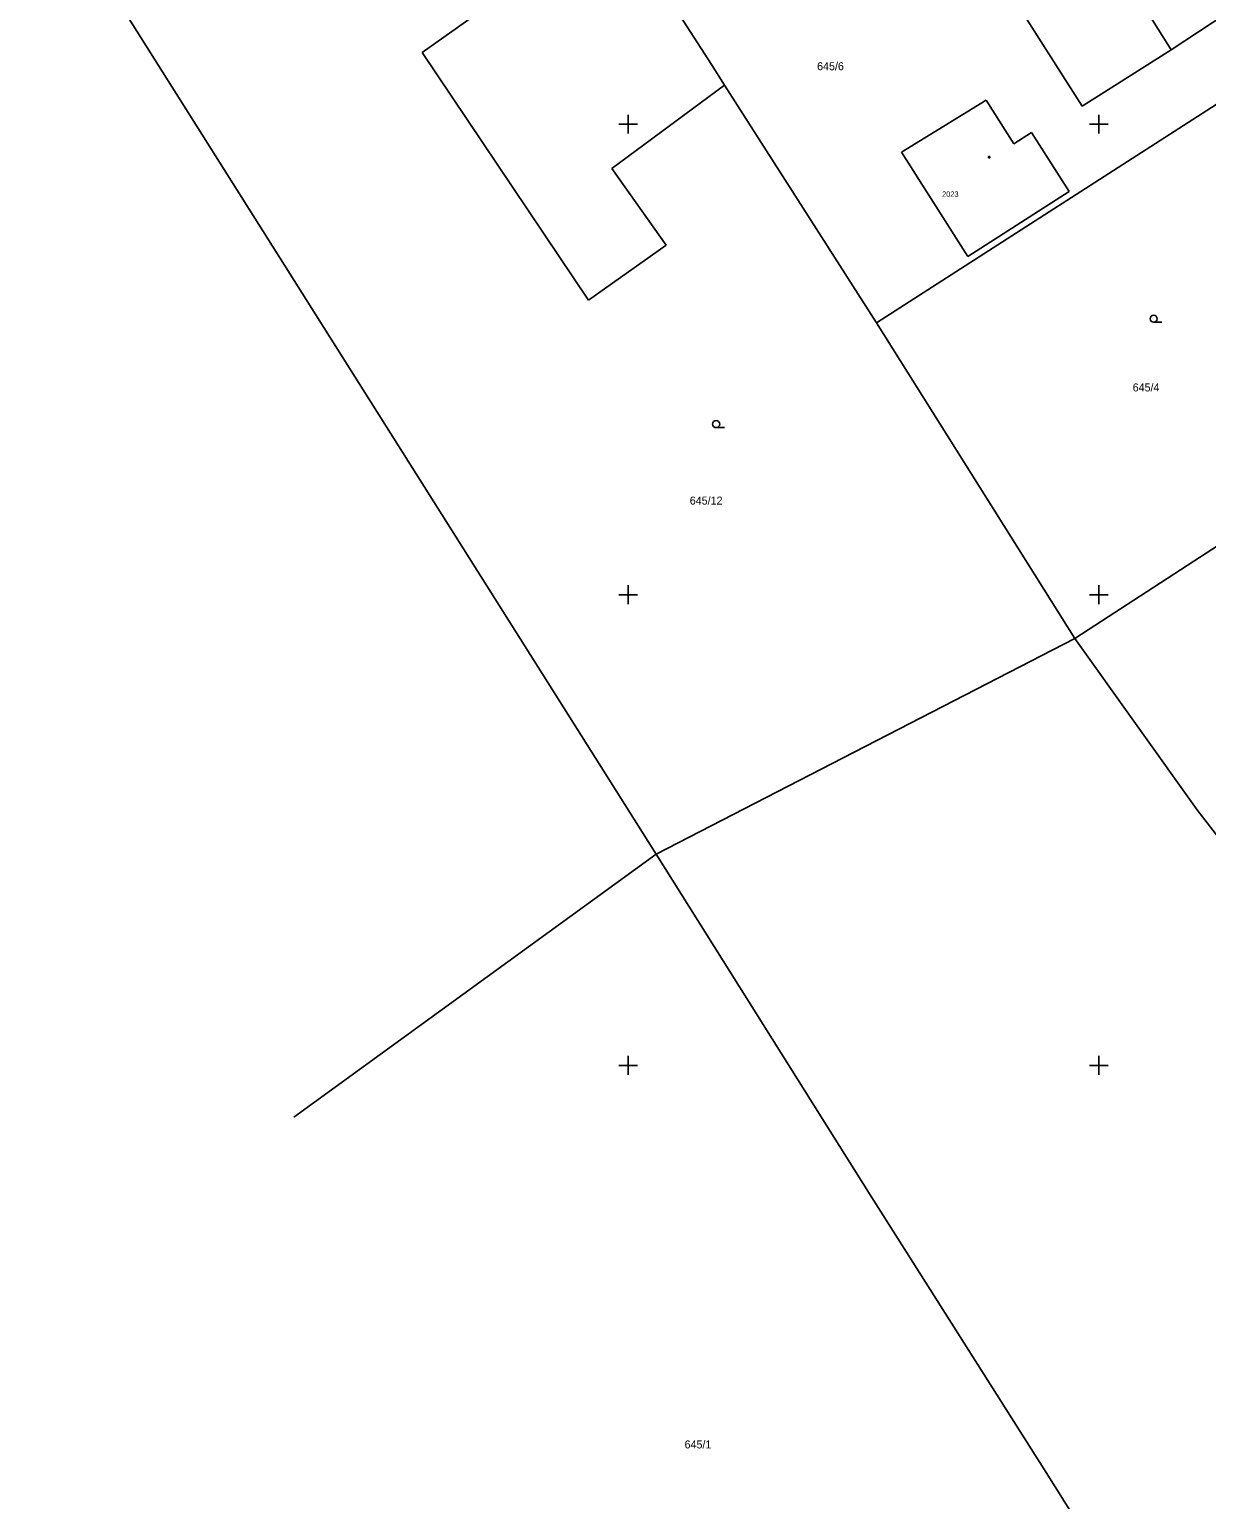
# Model space of a CAD drawing. Extents: x -492811 to -492366, y -1127107 to -1126748.
# Drawn here: x -492805.4 to -492755.4, y -1127038.5 to -1126976 of the extents above; entities that cross this region are included whole.
import ezdxf

# ---------------------------------------------------------------- set-up
doc = ezdxf.new("R2010")
doc.units = 0
doc.layers.add('katastrální mapa', color=7, linetype='Continuous')
doc.layers.add('síť', color=7, linetype='Continuous')

msp = doc.modelspace()

# ---------------------------------------------------------------- linework, layer by layer
at = {"layer": 'katastrální mapa'}
for p, q in [((-492805.44, -1126968.8), (-492778.81, -1127011.02)), ((-492756.93, -1126976.84), (-492749.29, -1126971.81)), ((-492788.75, -1126976.96), (-492782.73, -1126972.68)), ((-492764.95, -1126972.56), (-492760.7, -1126979.24)), ((-492759.68, -1126972.45), (-492756.93, -1126976.84)), ((-492778.08, -1126974.94), (-492776.46, -1126977.47)), ((-492769.44, -1126988.44), (-492749.85, -1126975.85)), ((-492788.75, -1126976.96), (-492781.68, -1126987.48)), ((-492759.05, -1126978.19), (-492756.93, -1126976.84)), ((-492775.91, -1126978.34), (-492776.46, -1126977.47)), ((-492780.69, -1126981.89), (-492775.91, -1126978.34)), ((-492775.91, -1126978.34), (-492769.44, -1126988.44)), ((-492760.7, -1126979.24), (-492759.05, -1126978.19)), ((-492768.39, -1126981.19), (-492764.79, -1126978.98)), ((-492764.79, -1126978.98), (-492763.61, -1126980.84)), ((-492763.61, -1126980.84), (-492762.86, -1126980.36)), ((-492762.86, -1126980.36), (-492761.26, -1126982.87)), ((-492768.39, -1126981.19), (-492765.56, -1126985.62)), ((-492764.69, -1126981.38), (-492764.63, -1126981.38)), ((-492764.69, -1126981.44), (-492764.69, -1126981.38)), ((-492764.63, -1126981.44), (-492764.69, -1126981.44)), ((-492764.63, -1126981.38), (-492764.63, -1126981.44)), ((-492778.38, -1126985.14), (-492780.69, -1126981.89)), ((-492765.56, -1126985.62), (-492761.26, -1126982.87)), ((-492781.68, -1126987.48), (-492778.38, -1126985.14)), ((-492769.44, -1126988.44), (-492761.02, -1127001.86)), ((-492757.67, -1126988.42), (-492757.32, -1126988.42)), ((-492776.26, -1126992.9), (-492775.91, -1126992.9)), ((-492761.02, -1127001.86), (-492748.84, -1126993.95)), ((-492778.81, -1127011.02), (-492761.02, -1127001.86)), ((-492761.02, -1127001.86), (-492755.79, -1127009.18)), ((-492755.79, -1127009.18), (-492752.22, -1127013.81)), ((-492794.2, -1127022.2), (-492778.81, -1127011.02)), ((-492769.64, -1127025.62), (-492778.81, -1127011.02)), ((-492769.64, -1127025.62), (-492762.23, -1127037.31)), ((-492762.23, -1127037.31), (-492759.45, -1127041.72))]:
    msp.add_line(p, q, dxfattribs=at)
for centre in [(-492757.67, -1126988.27), (-492776.26, -1126992.75)]:
    msp.add_circle(centre, 0.15, dxfattribs=at)
at = {"layer": 'síť'}
for p, q in [((-492780, -1126979.6), (-492780, -1126980.4)), ((-492760, -1126979.6), (-492760, -1126980.4)), ((-492780.4, -1126980), (-492779.6, -1126980)), ((-492760.4, -1126980), (-492759.6, -1126980)), ((-492780, -1126999.6), (-492780, -1127000.4)), ((-492760, -1126999.6), (-492760, -1127000.4)), ((-492780.4, -1127000), (-492779.6, -1127000)), ((-492760.4, -1127000), (-492759.6, -1127000)), ((-492780, -1127019.6), (-492780, -1127020.4)), ((-492760, -1127019.6), (-492760, -1127020.4)), ((-492780.4, -1127020), (-492779.6, -1127020)), ((-492760.4, -1127020), (-492759.6, -1127020))]:
    msp.add_line(p, q, dxfattribs=at)

# ---------------------------------------------------------------- texts
at = {"layer": 'katastrální mapa'}
for s, height, p in [('645/6', 0.34, (-492771.97, -1126977.71)), ('2023', 0.228, (-492766.66, -1126983.09)), ('645/4', 0.34, (-492758.56, -1126991.36)), ('645/12', 0.34, (-492777.38, -1126996.17)), ('645/1', 0.34, (-492777.6, -1127036.28))]:
    msp.add_text(s, height=height, dxfattribs=at).set_placement(p)

doc.saveas('drawing.dxf')
